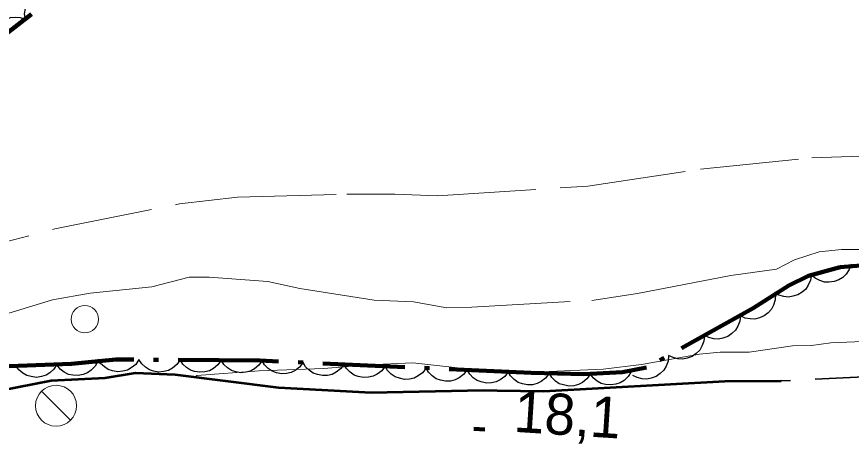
# Model space of a CAD drawing. Extents: x 386081 to 389416, y 5130568 to 5134082.
# Drawn here: x 387771.9 to 387832.9, y 5132439 to 5132470.3 of the extents above; entities that cross this region are included whole.
import ezdxf

# ---------------------------------------------------------------- set-up
doc = ezdxf.new("R2010")
doc.units = 0
doc.header["$LTSCALE"] = 1.2
for name, pattern in [('DOT_DASHED', [7.7, 5, -1.2, 0.3, -1.2]), ('LONG_DASHED', [7.5, 6, -1.5]), ('MEDIUM_DASHED', [4.5, 3, -1.5])]:
    doc.linetypes.add(name, pattern=pattern)
for name, color, linetype, lineweight in [('2', 7, 'Continuous', 13), ('21', 7, 'LONG_DASHED', 35), ('3', 7, 'Continuous', 140), ('36', 7, 'Continuous', 13), ('44', 7, 'Continuous', 25)]:
    doc.layers.add(name, color=color, linetype=linetype, lineweight=lineweight)

msp = doc.modelspace()

# ---------------------------------------------------------------- linework, layer by layer
at = {"layer": '2', "linetype": 'LONG_DASHED'}
for points in [[(387765.79, 5132452.44), (387774.66, 5132454.78), (387783.78, 5132456.61), (387788.02, 5132457.1), (387796.01, 5132457.33), (387799.5, 5132457.32), (387802.62, 5132457.19), (387813.61, 5132457.91), (387821.86, 5132459.14), (387829.98, 5132459.99), (387833.6, 5132460.1)], [(387781.76, 5132450.54), (387784.47, 5132451.24), (387785.95, 5132451.24), (387790.24, 5132450.92), (387792.57, 5132450.41), (387798, 5132449.57), (387800.88, 5132449.45), (387803.32, 5132449.01), (387805.14, 5132449.05), (387813.9, 5132449.55), (387817.25, 5132450.05), (387824.06, 5132451.36), (387827.41, 5132451.84), (387828.71, 5132452.51), (387830.53, 5132453.09), (387832.16, 5132453.28), (387843.19, 5132453.29)]]:
    msp.add_lwpolyline(points, dxfattribs=at)
at = {"layer": '2'}
for points in [[(387595.78, 5132354.61), (387596.25, 5132355.95), (387598.89, 5132358.28), (387632.06, 5132382.54), (387636.36, 5132385.22), (387647.69, 5132391.91), (387663.55, 5132401.63), (387670.59, 5132406.32), (387676.35, 5132409.76), (387690.6, 5132418.7), (387697.88, 5132422.84), (387700.46, 5132423.92), (387709.45, 5132427.98), (387714.62, 5132429.92), (387724.45, 5132433.25), (387748.22, 5132441.01), (387752.95, 5132442.88), (387758.29, 5132444.63), (387774.49, 5132449.59), (387777.24, 5132450.08), (387781.76, 5132450.54)], [(387784.91, 5132443.94), (387785.03, 5132444.06), (387789.59, 5132444.4), (387794.33, 5132444.56), (387797.58, 5132444.83), (387800.83, 5132444.98), (387806.5, 5132444.34), (387809.68, 5132444.3), (387814.74, 5132444.52), (387817.54, 5132444.85), (387821.78, 5132445.62), (387823.28, 5132445.76), (387825.4, 5132445.77), (387828.58, 5132446.23), (387829.95, 5132446.24), (387831.38, 5132446.44), (387838.36, 5132446.73)]]:
    msp.add_lwpolyline(points, dxfattribs=at)
at = {"layer": '21', "linetype": 'Continuous', "lineweight": 53}
for points in [[(387768.17, 5132442.46), (387774.39, 5132443.7), (387778.35, 5132443.88), (387780.56, 5132444.26), (387783.45, 5132444.12), (387791.01, 5132443.17), (387797.79, 5132442.8), (387805.99, 5132442.99), (387806.99, 5132442.95)], [(387806.99, 5132442.95), (387810.39, 5132442.9), (387823.63, 5132443.63), (387827.75, 5132443.66)]]:
    msp.add_lwpolyline(points, dxfattribs=at)
at = {"layer": '21', "linetype": 'MEDIUM_DASHED'}
msp.add_lwpolyline([(387839.21, 5132444.24), (387827.75, 5132443.66)], dxfattribs=at)
at = {"layer": '3'}
msp.add_line((387805.29, 5132440.16), (387806.08, 5132440.11), dxfattribs=at)
at = {"layer": '36'}
msp.add_line((387775.82, 5132440.77), (387773.7, 5132442.91), dxfattribs=at)
for centre, radius in [((387776.858, 5132448.17), 1), ((387774.75, 5132441.841), 1.5)]:
    msp.add_circle(centre, radius, dxfattribs=at)
at = {"layer": '44'}
for points in [[(387772.51, 5132470.1), (387772.45, 5132470.51), (387772.52, 5132470.91), (387772.61, 5132471.23), (387772.8, 5132471.52), (387773.05, 5132471.79), (387773.38, 5132472), (387773.67, 5132472.14), (387774.02, 5132472.2), (387774.39, 5132472.19), (387774.74, 5132472.11)], [(387770.12, 5132468.29), (387770.09, 5132468.7), (387770.18, 5132469.1), (387770.3, 5132469.41), (387770.51, 5132469.69), (387770.78, 5132469.94), (387771.12, 5132470.12), (387771.42, 5132470.24), (387771.77, 5132470.27), (387772.14, 5132470.24), (387772.48, 5132470.13)], [(387832.85, 5132452.2), (387832.72, 5132451.81), (387832.49, 5132451.48), (387832.26, 5132451.23), (387831.96, 5132451.06), (387831.61, 5132450.93), (387831.23, 5132450.89), (387830.9, 5132450.89), (387830.57, 5132451), (387830.24, 5132451.17), (387829.96, 5132451.4)], [(387829.95, 5132451.44), (387829.89, 5132451.03), (387829.72, 5132450.66), (387829.54, 5132450.38), (387829.28, 5132450.15), (387828.96, 5132449.96), (387828.6, 5132449.85), (387828.28, 5132449.79), (387827.93, 5132449.83), (387827.57, 5132449.94), (387827.26, 5132450.12)], [(387827.32, 5132450.01), (387827.31, 5132449.59), (387827.18, 5132449.2), (387827.03, 5132448.91), (387826.79, 5132448.65), (387826.5, 5132448.42), (387826.15, 5132448.27), (387825.83, 5132448.18), (387825.48, 5132448.19), (387825.12, 5132448.25), (387824.79, 5132448.4)], [(387824.76, 5132448.45), (387824.72, 5132448.03), (387824.57, 5132447.66), (387824.41, 5132447.37), (387824.15, 5132447.12), (387823.85, 5132446.92), (387823.49, 5132446.79), (387823.17, 5132446.71), (387822.82, 5132446.74), (387822.46, 5132446.83), (387822.14, 5132446.99)], [(387822.14, 5132446.99), (387822.1, 5132446.57), (387821.95, 5132446.19), (387821.79, 5132445.91), (387821.53, 5132445.66), (387821.23, 5132445.45), (387820.87, 5132445.33), (387820.55, 5132445.25), (387820.2, 5132445.28), (387819.84, 5132445.36), (387819.52, 5132445.53)], [(387777.81, 5132445.1), (387777.61, 5132444.73), (387777.32, 5132444.45), (387777.06, 5132444.25), (387776.73, 5132444.13), (387776.37, 5132444.06), (387775.99, 5132444.08), (387775.66, 5132444.14), (387775.35, 5132444.31), (387775.06, 5132444.53), (387774.83, 5132444.81)], [(387780.81, 5132445.22), (387780.57, 5132444.87), (387780.25, 5132444.62), (387779.97, 5132444.45), (387779.63, 5132444.36), (387779.26, 5132444.33), (387778.88, 5132444.4), (387778.57, 5132444.49), (387778.28, 5132444.69), (387778.01, 5132444.94), (387777.81, 5132445.24)], [(387783.81, 5132445.19), (387783.57, 5132444.85), (387783.25, 5132444.6), (387782.97, 5132444.43), (387782.63, 5132444.34), (387782.26, 5132444.31), (387781.88, 5132444.38), (387781.57, 5132444.47), (387781.28, 5132444.66), (387781.01, 5132444.92), (387780.81, 5132445.22)], [(387786.81, 5132445.17), (387786.57, 5132444.83), (387786.25, 5132444.57), (387785.97, 5132444.4), (387785.63, 5132444.32), (387785.26, 5132444.29), (387784.88, 5132444.35), (387784.57, 5132444.44), (387784.28, 5132444.64), (387784.01, 5132444.89), (387783.81, 5132445.19)], [(387789.81, 5132445.15), (387789.57, 5132444.8), (387789.25, 5132444.55), (387788.97, 5132444.38), (387788.63, 5132444.29), (387788.26, 5132444.26), (387787.88, 5132444.33), (387787.57, 5132444.42), (387787.28, 5132444.62), (387787.01, 5132444.87), (387786.81, 5132445.17)], [(387792.8, 5132445.01), (387792.55, 5132444.67), (387792.23, 5132444.43), (387791.94, 5132444.27), (387791.59, 5132444.2), (387791.22, 5132444.18), (387790.85, 5132444.26), (387790.54, 5132444.37), (387790.25, 5132444.57), (387789.99, 5132444.84), (387789.81, 5132445.14)], [(387819.52, 5132445.53), (387819.48, 5132445.11), (387819.33, 5132444.73), (387819.17, 5132444.44), (387818.91, 5132444.2), (387818.61, 5132443.99), (387818.25, 5132443.86), (387817.93, 5132443.79), (387817.58, 5132443.82), (387817.22, 5132443.9), (387816.9, 5132444.06)], [(387774.82, 5132444.87), (387774.6, 5132444.52), (387774.29, 5132444.25), (387774.02, 5132444.07), (387773.68, 5132443.97), (387773.32, 5132443.92), (387772.94, 5132443.97), (387772.62, 5132444.05), (387772.32, 5132444.23), (387772.04, 5132444.47), (387771.82, 5132444.76)], [(387795.8, 5132444.87), (387795.55, 5132444.54), (387795.22, 5132444.3), (387794.93, 5132444.14), (387794.59, 5132444.06), (387794.22, 5132444.05), (387793.85, 5132444.13), (387793.54, 5132444.23), (387793.25, 5132444.44), (387792.99, 5132444.7), (387792.8, 5132445.01)], [(387798.8, 5132444.74), (387798.55, 5132444.4), (387798.22, 5132444.16), (387797.93, 5132444), (387797.59, 5132443.93), (387797.22, 5132443.91), (387796.84, 5132443.99), (387796.53, 5132444.09), (387796.25, 5132444.3), (387795.99, 5132444.56), (387795.8, 5132444.87)], [(387801.79, 5132444.6), (387801.54, 5132444.26), (387801.22, 5132444.02), (387800.93, 5132443.86), (387800.58, 5132443.79), (387800.21, 5132443.77), (387799.84, 5132443.86), (387799.53, 5132443.96), (387799.24, 5132444.16), (387798.98, 5132444.43), (387798.8, 5132444.74)], [(387804.79, 5132444.46), (387804.54, 5132444.13), (387804.21, 5132443.89), (387803.92, 5132443.73), (387803.58, 5132443.65), (387803.21, 5132443.64), (387802.84, 5132443.72), (387802.53, 5132443.82), (387802.24, 5132444.03), (387801.98, 5132444.29), (387801.79, 5132444.6)], [(387807.79, 5132444.33), (387807.54, 5132443.99), (387807.21, 5132443.75), (387806.92, 5132443.59), (387806.58, 5132443.52), (387806.21, 5132443.5), (387805.83, 5132443.58), (387805.52, 5132443.69), (387805.24, 5132443.89), (387804.98, 5132444.16), (387804.79, 5132444.46)], [(387810.78, 5132444.19), (387810.53, 5132443.86), (387810.21, 5132443.61), (387809.92, 5132443.46), (387809.57, 5132443.38), (387809.2, 5132443.37), (387808.83, 5132443.45), (387808.52, 5132443.55), (387808.24, 5132443.76), (387807.97, 5132444.02), (387807.79, 5132444.33)], [(387813.78, 5132444.14), (387813.54, 5132443.8), (387813.22, 5132443.55), (387812.93, 5132443.39), (387812.59, 5132443.3), (387812.22, 5132443.28), (387811.84, 5132443.36), (387811.53, 5132443.45), (387811.24, 5132443.65), (387810.98, 5132443.91), (387810.78, 5132444.22)], [(387816.78, 5132444.33), (387816.56, 5132443.98), (387816.26, 5132443.7), (387815.99, 5132443.52), (387815.65, 5132443.41), (387815.29, 5132443.36), (387814.91, 5132443.4), (387814.59, 5132443.47), (387814.29, 5132443.65), (387814, 5132443.89), (387813.78, 5132444.17)]]:
    msp.add_lwpolyline(points, dxfattribs=at)
at = {"layer": '44', "linetype": 'DOT_DASHED', "lineweight": 90}
for points in [[(387693.68, 5132448.88), (387695.39, 5132448.41), (387699.66, 5132446.12), (387701.5, 5132445.04), (387703.45, 5132444.08), (387705.89, 5132443.37), (387707.72, 5132443.01), (387715.26, 5132443.32), (387718.8, 5132443.96), (387722.1, 5132444.84), (387728.93, 5132447.09), (387736.25, 5132449.84), (387740.28, 5132451.21), (387743.2, 5132452.45), (387750.4, 5132455.8), (387754.42, 5132457.91), (387764.66, 5132463.85), (387767.47, 5132465.94), (387769.79, 5132468.03), (387772.96, 5132470.5)], [(387847.71, 5132447.1), (387842.69, 5132448.14), (387840.86, 5132447.76), (387839.41, 5132447.75), (387837.88, 5132448.01), (387836.82, 5132450.96), (387836.22, 5132451.41), (387835.01, 5132451.91), (387833.56, 5132452.09), (387832.05, 5132451.98), (387829.74, 5132451.34), (387828.3, 5132450.63), (387825.69, 5132448.97), (387817.91, 5132444.63), (387816.14, 5132444.3), (387813.33, 5132444.15), (387809.48, 5132444.25), (387789.68, 5132445.15), (387779.11, 5132445.23), (387775.88, 5132444.91), (387769.76, 5132444.69)]]:
    msp.add_lwpolyline(points, dxfattribs=at)

# ---------------------------------------------------------------- texts
at = {"layer": '3'}
msp.add_text('18,1   ', height=3, rotation=356.338, dxfattribs=at).set_placement((387808.15, 5132439.94))

doc.saveas('drawing.dxf')
